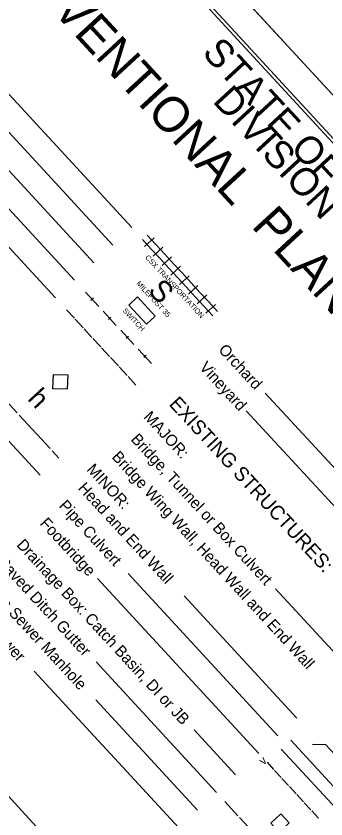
# Model space of a CAD drawing. Extents: x 1695041 to 1706254, y 786537 to 798223.
# Drawn here: x 1700861 to 1701339, y 791621 to 792859 of the extents above; entities that cross this region are included whole.
import ezdxf

# ---------------------------------------------------------------- set-up
doc = ezdxf.new("R2010")
doc.units = 0
for name, color, linetype in [('Prop EOT', 7, 'Continuous'), ('Sheet Cutting Line CELL', 7, 'Continuous'), ('Sheet Plot Border Inside CELL', 7, 'Continuous'), ('Sheet Plot Border Outside CELL', 7, 'Continuous'), ('Sheet Symbology CELL', 7, 'Continuous')]:
    doc.layers.add(name, color=color, linetype=linetype)

msp = doc.modelspace()

# ---------------------------------------------------------------- linework, layer by layer
at = {"layer": 'Prop EOT'}
msp.add_lwpolyline([(1700918.9, 792306.9), (1700941, 792306), (1700940.2, 792283.9), (1700918, 792284.8)], close=True, dxfattribs=at)
at = {"layer": 'Sheet Cutting Line CELL'}
msp.add_line((1702487.1, 791505.7), (1700202.7, 793980.5), dxfattribs=at)
at = {"layer": 'Sheet Plot Border Inside CELL'}
msp.add_lwpolyline([(1698636.7, 792499.7), (1700897.4, 790050.6), (1702448, 791481.9), (1700187.3, 793931)], close=True, dxfattribs=at)
at = {"layer": 'Sheet Plot Border Outside CELL'}
msp.add_lwpolyline([(1698586.1, 792488.3), (1700870.5, 790013.5), (1702487.1, 791505.7), (1700202.7, 793980.5)], close=True, dxfattribs=at)
at = {"layer": 'Sheet Symbology CELL'}
for p, q in [((1700980.9, 792479), (1700689.4, 792794.9)), ((1701039.7, 792533.3), (1700824.8, 792766.1)), ((1701010.3, 792506.1), (1700807.5, 792725.9)), ((1700951.5, 792451.9), (1700726.1, 792696.1)), ((1700922.2, 792424.7), (1700696.7, 792668.9)), ((1700922.2, 792424.7), (1700696.7, 792668.9)), ((1701056.2, 792514.7), (1701069.7, 792500)), ((1701059.3, 792504), (1701074, 792517.6)), ((1701063.5, 792521.5), (1701077.1, 792506.8)), ((1701069.7, 792500), (1701083.3, 792485.3)), ((1701072.9, 792489.3), (1701087.6, 792502.9)), ((1701077.1, 792506.8), (1701090.7, 792492.1)), ((1701086.4, 792474.6), (1701101.1, 792488.2)), ((1701090.7, 792492.1), (1701104.2, 792477.4)), ((1701083.3, 792485.3), (1701096.9, 792470.7)), ((1701100, 792459.9), (1701114.7, 792473.5)), ((1701104.2, 792477.4), (1701117.8, 792462.7)), ((1701096.9, 792470.7), (1701110.4, 792456)), ((1701117.8, 792462.7), (1701131.4, 792448)), ((1701110.4, 792456), (1701124, 792441.3)), ((1701113.6, 792445.2), (1701128.2, 792458.8)), ((1701124, 792441.3), (1701137.6, 792426.6)), ((1701127.1, 792430.5), (1701141.8, 792444.1)), ((1701131.4, 792448), (1701144.9, 792433.3)), ((1700968.4, 792433.7), (1700988.7, 792411.6)), ((1700980.4, 792424.3), (1700976.7, 792421)), ((1701137.6, 792426.6), (1701151.1, 792411.9)), ((1701140.7, 792415.8), (1701155.4, 792429.4)), ((1701144.9, 792433.3), (1701158.5, 792418.6)), ((1701151.1, 792411.9), (1701164.7, 792397.2)), ((1701154.2, 792401.1), (1701168.9, 792414.7)), ((1701158.5, 792418.6), (1701172.1, 792404)), ((1700939, 792406.5), (1700951.2, 792393.3)), ((1700995.5, 792404.3), (1701015.8, 792382.2)), ((1700952.5, 792391.8), (1700964.7, 792378.6)), ((1701007.5, 792394.9), (1701003.8, 792391.6)), ((1700966.1, 792377.1), (1700978.3, 792363.9)), ((1701022.6, 792374.9), (1701043, 792352.8)), ((1700979.7, 792362.4), (1700991.9, 792349.2)), ((1701034.6, 792365.6), (1701031, 792362.2)), ((1700993.2, 792347.8), (1701005.4, 792334.5)), ((1701049.7, 792345.5), (1701070.1, 792323.4)), ((1701006.8, 792333.1), (1701019, 792319.8)), ((1701061.8, 792336.2), (1701058.1, 792332.8)), ((1701020.4, 792318.4), (1701032.6, 792305.1)), ((1701033.9, 792303.7), (1701046.1, 792290.4)), ((1700815.2, 792299.1), (1700862.7, 792247.6)), ((1701523.8, 791976.6), (1701245.8, 792277.7)), ((1700786.4, 792272.6), (1700898.4, 792151.3)), ((1701494.5, 791949.4), (1701216.4, 792250.6)), ((1700866, 792244), (1700913.5, 792192.5)), ((1700916.9, 792188.9), (1700927.1, 792177.8)), ((1701235.8, 791722.4), (1700986.9, 791992)), ((1701265.2, 791749.5), (1701034.3, 791999.6)), ((1701376.2, 791852.1), (1701261.7, 791976.1)), ((1701294.6, 791776.7), (1701120.5, 791965.2)), ((1701170.5, 791662.1), (1700984.7, 791863.4)), ((1701111.7, 791607.9), (1700889, 791849.2)), ((1701141.1, 791635), (1700984.2, 791805)), ((1701199.9, 791689.3), (1701135.8, 791758.6)), ((1701285.1, 791742.7), (1701397, 791621.4)), ((1701318.8, 791736.9), (1701338.8, 791736.1)), ((1701338.8, 791736.1), (1701394.8, 791675.5)), ((1701270.4, 791729.1), (1701382.4, 791607.8)), ((1701248.4, 791708.7), (1701258.6, 791697.7)), ((1700997.9, 791495.3), (1700809.8, 791699.1)), ((1701259.9, 791696.2), (1701270.1, 791685.2)), ((1701271.5, 791683.8), (1701281.6, 791672.7)), ((1701283, 791671.3), (1701293.2, 791660.2)), ((1701294.5, 791658.8), (1701304.7, 791647.7)), ((1701183.1, 791648.5), (1701203.4, 791626.4)), ((1701306, 791646.3), (1701316.2, 791635.3)), ((1701317.6, 791633.8), (1701327.8, 791622.8)), ((1701206.2, 791623.5), (1701226.5, 791601.4))]:
    msp.add_line(p, q, dxfattribs=at)
for points in [[(1702427.3, 791496.8), (1700392.5, 793701.2), (1698850.9, 792278.2), (1700885.7, 790073.8)], [(1701048.7, 792426.2), (1701075.8, 792396.8), (1701062.4, 792384.4), (1701035.3, 792413.8)], [(1701254.1, 791614.8), (1701267.2, 791600.7), (1701282.8, 791615.1), (1701269.7, 791629.3)]]:
    msp.add_lwpolyline(points, close=True, dxfattribs=at)

# ---------------------------------------------------------------- texts
for s, height, rotation, p in [('CONVENTIONAL  PLAN SHEET SYMBOLS', 54.401, 312.7091, (1700806.2, 792986.3)), ('STATE OF NORTH CAROLINA', 42.838, 312.7091, (1701146.7, 792801.6)), ('DIVISION OF HIGHWAYS', 42.838, 312.7091, (1701163.1, 792727.4)), ('CSX TRANSPORTATION', 8, 312.7091, (1701059.8, 792486.6)), ('MILEPOST 35', 8, 312.7091, (1701046.3, 792446.4)), ('S', 33, 312.7091, (1701063.4, 792435)), ('SWITCH', 8, 312.7091, (1701025.1, 792404.5)), ('Orchard', 17.5, 312.7091, (1701172.4, 792343.9)), ('Vineyard', 17.5, 312.7091, (1701143, 792316.8)), ('h', 30, 312.7091, (1700877.6, 792268.3)), ('EXISTING STRUCTURES:', 22, 312.7091, (1701096, 792260.1)), ('MAJOR:', 17.5, 312.7091, (1701056.8, 792240.4)), ('Bridge, Tunnel or Box Culvert', 17.5, 312.7091, (1701037.2, 792205.9)), ('Bridge Wing Wall, Head Wall and End Wall', 17.5, 312.7091, (1701007.8, 792178.7)), ('MINOR:', 17.5, 312.7091, (1700969.1, 792159.4)), ('Head and End Wall', 17.5, 312.7091, (1700955.6, 792130.5)), ('Pipe Culvert', 17.5, 312.7091, (1700926.2, 792103.4)), ('Footbridge', 17.5, 312.7091, (1700896.8, 792076.2)), ('Drainage Box: Catch Basin, DI or JB', 17.5, 312.7091, (1700860.9, 792043.1)), ('Paved Ditch Gutter', 17.5, 312.7091, (1700831.5, 792015.9)), ('Storm Sewer Manhole', 17.5, 312.7091, (1700802.1, 791988.8)), ('Storm Sewer', 17.5, 312.7091, (1700772.7, 791961.7)), ('v', 13.2, 42.4682, (1701242.9, 791703.7))]:
    msp.add_text(s, height=height, rotation=rotation, dxfattribs=at).set_placement(p)

doc.saveas('drawing.dxf')
